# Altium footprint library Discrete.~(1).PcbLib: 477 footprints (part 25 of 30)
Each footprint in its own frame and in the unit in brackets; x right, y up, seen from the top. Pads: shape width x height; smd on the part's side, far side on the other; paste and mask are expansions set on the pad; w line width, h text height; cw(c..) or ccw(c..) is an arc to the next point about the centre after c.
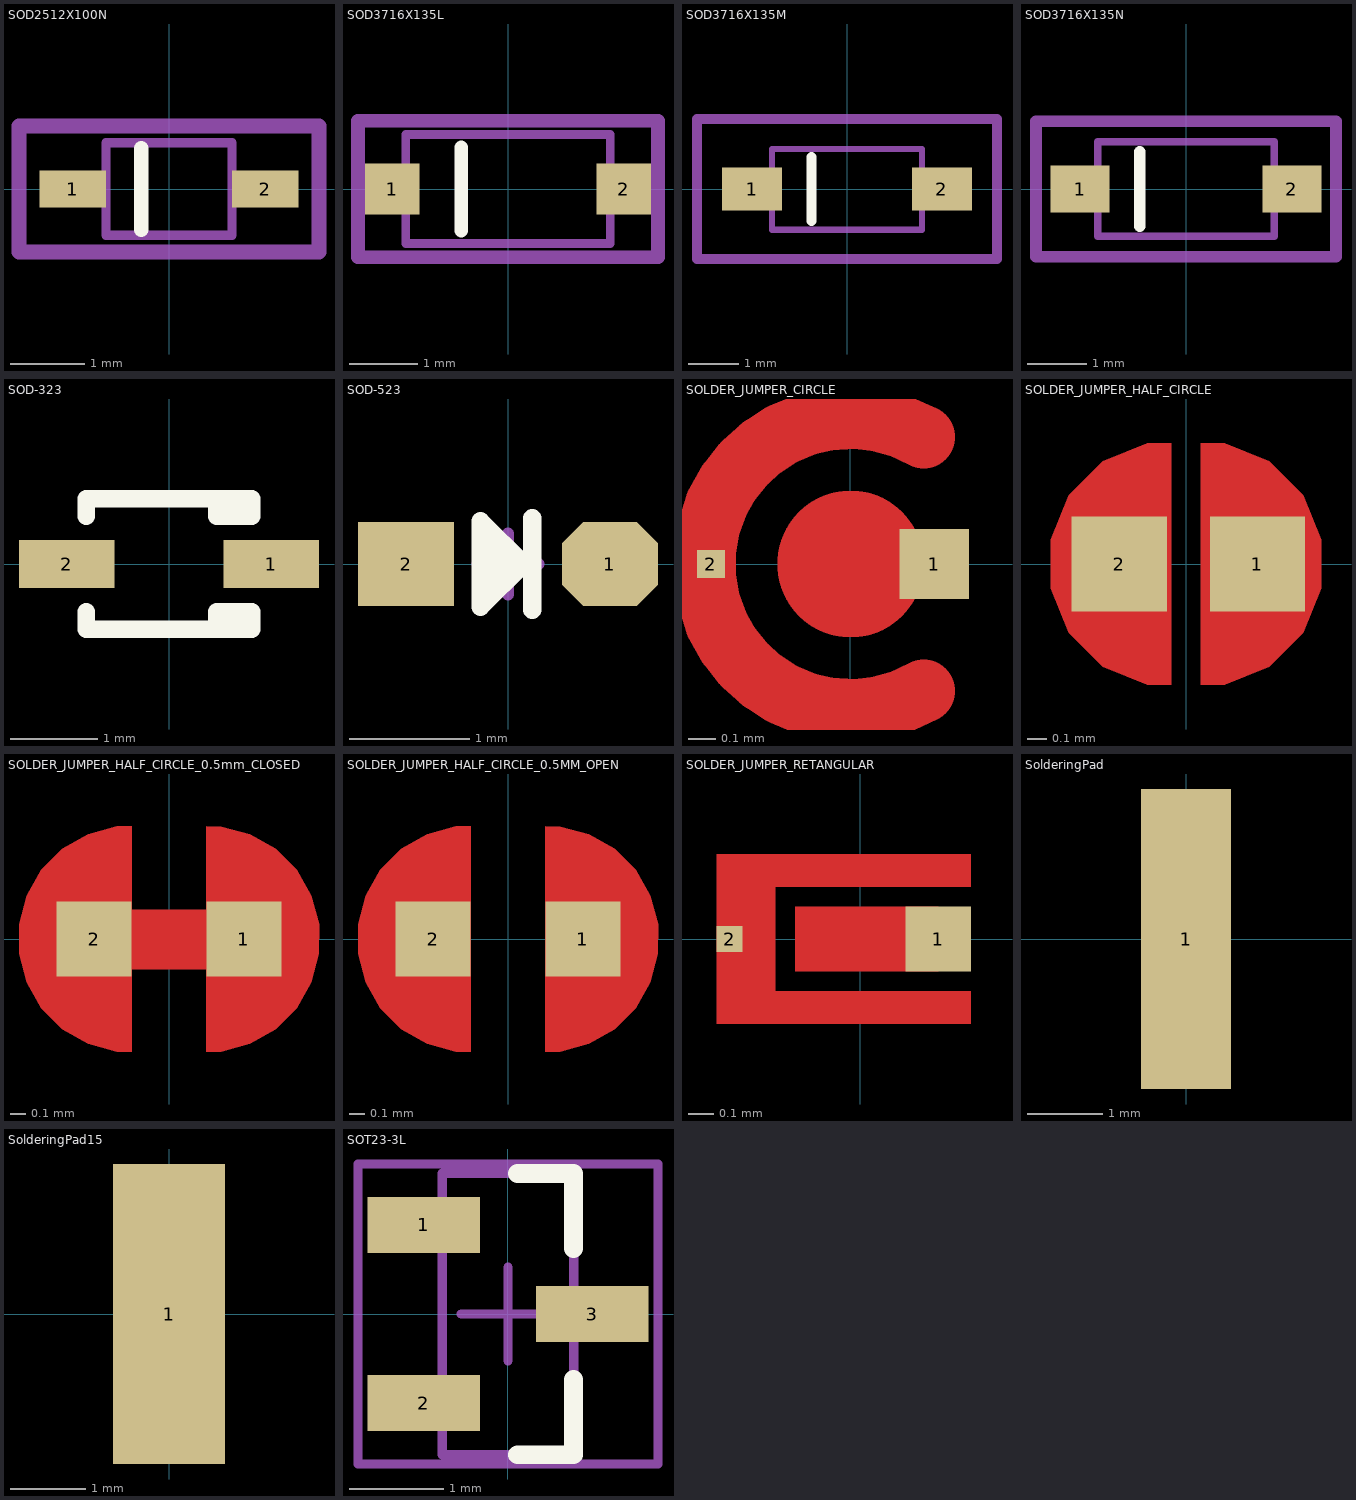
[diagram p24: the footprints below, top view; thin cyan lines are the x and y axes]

## SOD2512X100N [mm] "SOD Diode: SOD-323"
height 1
pads (2):
  rect 0.9x0.5 smd: 1(-1.3,0) 2(1.3,0)
Top Overlay:
  lines w0.2: -0.375,-0.55 -0.375,0.55
Mechanical 13:
  lines w0.127: -0.85,-0.625 -0.85,0.625 0.85,0.625 0.85,-0.625 -0.85,-0.625
Mechanical 15:
  lines w0.2: -2.025,-0.85 -2.025,0.85 2.025,0.85 2.025,-0.85 -2.025,-0.85
3D body "SOD-323.STEP": height 1, standoff 0.04, extent -1.324,-0.65 1.324,0.65

## SOD3716X135L [mm] "SOD Diode: SOD-123"
pads (2):
  rect 0.8x0.75 smd: 1(-1.7,0) 2(1.7,0)
Top Overlay:
  lines w0.2: -0.686,-0.61 -0.686,0.61
Mechanical 13:
  lines w0.127: -1.5,-0.8 1.5,-0.8 1.5,0.8 -1.5,0.8 -1.5,-0.8
Mechanical 15:
  lines w0.2: -2.2,-1 2.2,-1 2.2,1 -2.2,1 -2.2,-1
3D body "SOD-123.STEP": height 1.22, standoff 0, extent -1.85,-0.8 1.85,0.8

## SOD3716X135M [mm] "SOD Diode: SOD-123"
pads (2):
  rect 1.2x0.85 smd: 1(-1.9,0) 2(1.9,0)
Top Overlay:
  lines w0.2: -0.711,-0.635 -0.711,0.635
Mechanical 13:
  lines w0.127: -1.5,-0.813 -1.5,0.8 1.5,0.8 1.5,-0.813 -1.5,-0.813
Mechanical 15:
  lines w0.2: -3,-1.4 -3,1.4 3,1.4 3,-1.4 -3,-1.4
3D body "SOD-123.STEP": height 1.22, standoff 0, extent -1.85,-0.8 1.85,0.8

## SOD3716X135N [mm] "SOD Diode: SOD-123"
pads (2):
  rect 1x0.8 smd: 1(-1.8,0) 2(1.8,0)
Top Overlay:
  lines w0.2: -0.787,-0.635 -0.787,0.635
Mechanical 13:
  lines w0.127: -1.5,-0.8 1.5,-0.8 1.5,0.8 -1.5,0.8 -1.5,-0.8
Mechanical 15:
  lines w0.2: -2.55,-1.15 2.55,-1.15 2.55,1.15 -2.55,1.15 -2.55,-1.15
3D body "SOD-123.STEP": height 1.22, standoff 0, extent -1.85,-0.8 1.85,0.8

## SOD-323 [mm] "SOD-323/SC-76; 2 Leads; Body 1.7 x 1.3 mm, (LxW)"
height 1.1
pads (2):
  rect 1.1x0.55 smd: 1(1.175,0) 2(-1.175,0)
Top Overlay:
  lines w0.2: -0.95,-0.55 -0.95,-0.75 0.95,-0.75 0.95,-0.55 0.55,-0.55 0.55,-0.75 ; -0.95,0.55 -0.95,0.75 0.95,0.75 0.95,0.55 0.55,0.55 0.55,0.75
3D body "SOD-323.STEP": height 1, standoff 0.04, extent -1.337,-0.631 1.311,0.669

## SOD-523 [mm] "1.2x0.8X0.6mm（长宽高，不包括引脚）"
pads (2):
  oct 0.8x0.7 smd: 1(0.85,0)
  rect 0.8x0.7 smd: 2(-0.85,0)
Top Overlay:
  rectangle: -0.178,-0.178 0,0.178
  lines w0.152: -0.127,0 0.127,0 ; 0.203,-0.381 0.203,0.381 ; 0.127,0 -0.229,0.356 -0.229,-0.356 0.127,0
Mechanical 15:
  lines w0.1: -0.254,0 0.254,0 ; 0,-0.254 0,0.254
3D body "SOD-523.STEP": height 0.65, standoff 0.05, extent -0.8,-0.4 0.8,0.4

## SOIL_SENSOR_PATTERN_1 [mm]

## SOLDER_JUMPER_CIRCLE [mil]
pads (2):
  rect 10x10 smd: 1(12,0)
  rect 4x4 smd mask+0: 2(-20,0)
Top Layer:
  circle w19: c0,0 r1
  lines w9: 10.5,-18.19 cw(c0,0) 10.5,18.19
Top Solder:
  circle w40: c0,0 r7.07

## SOLDER_JUMPER_HALF_CIRCLE [mm]
pads (2):
  rect 0.5x0.5 smd: 1(0.375,0) 2(-0.35,0)
Top Layer:
  region: 0.076,-0.635 0.203,-0.635 0.436,-0.538 0.615,-0.36 0.711,-0.126 0.711,0.126 0.615,0.36 0.436,0.538 0.203,0.635 0.076,0.635
  region: -0.076,-0.635 -0.203,-0.635 -0.436,-0.538 -0.615,-0.36 -0.711,-0.126 -0.711,0.126 -0.615,0.36 -0.436,0.538 -0.203,0.635 -0.076,0.635
Top Solder:
  region: -0.076,-0.711 -0.17,-0.711 -0.351,-0.663 -0.513,-0.569 -0.645,-0.437 -0.739,-0.275 -0.787,-0.094 -0.787,0.094 -0.739,0.275 -0.645,0.437 -0.513,0.569 -0.351,0.663 -0.17,0.711 -0.076,0.711 0.076,0.711 0.17,0.711 0.351,0.663 0.513,0.569 0.645,0.437 0.739,0.275 0.787,0.094 0.787,-0.094 0.739,-0.275 0.645,-0.437 0.513,-0.569 0.351,-0.663 0.17,-0.711 0.076,-0.711

## SOLDER_JUMPER_HALF_CIRCLE_0.5mm_CLOSED [mm]
pads (2):
  rect 0.5x0.5 smd: 1(0.5,0) 2(-0.5,0)
Top Layer:
  region: 0.25,-0.75 0.349,-0.75 0.539,-0.699 0.711,-0.6 0.85,-0.461 0.949,-0.289 1,-0.099 1,0.099 0.949,0.289 0.85,0.461 0.711,0.6 0.539,0.699 0.349,0.75 0.25,0.75
  region: -0.25,-0.75 -0.349,-0.75 -0.539,-0.699 -0.711,-0.6 -0.85,-0.461 -0.949,-0.289 -1,-0.099 -1,0.099 -0.949,0.289 -0.85,0.461 -0.711,0.6 -0.539,0.699 -0.349,0.75 -0.25,0.75
  lines w0.4: -0.25,-0.003 0.492,-0.003
Top Solder:
  rectangle: -0.25,-0.25 0.25,0.25

## SOLDER_JUMPER_HALF_CIRCLE_0.5MM_OPEN [mm]
pads (2):
  rect 0.5x0.5 smd: 1(0.5,0) 2(-0.5,0)
Top Layer:
  region: -0.25,-0.75 -0.349,-0.75 -0.539,-0.699 -0.711,-0.6 -0.85,-0.461 -0.949,-0.289 -1,-0.099 -1,0.099 -0.949,0.289 -0.85,0.461 -0.711,0.6 -0.539,0.699 -0.349,0.75 -0.25,0.75
  region: 0.25,-0.75 0.349,-0.75 0.539,-0.699 0.711,-0.6 0.85,-0.461 0.949,-0.289 1,-0.099 1,0.099 0.949,0.289 0.85,0.461 0.711,0.6 0.539,0.699 0.349,0.75 0.25,0.75

## SOLDER_JUMPER_RETANGULAR [mil]
pads (2):
  rect 10x10 smd: 1(12,0)
  rect 4x4 smd mask+0: 2(-20,0)
Top Layer:
  rectangle: -22,-13 17,-8
  rectangle: -22,8 17,13
  rectangle: -22,-10 -13,10
  rectangle: -10,-5 12,5
Top Solder:
  rectangle: -25,-15 21,15

## SolderingPad [mm]
pads (1):
  rect 1.2x4 smd: 1(0,0)

## SolderingPad15 [mm]
pads (1):
  rect 1.5x4 smd: 1(0,0)

## SolderingPads [mm]

## SOT23-3L [mm] "SOT23, 3-Leads, Body 2.9x1.3mm, Pitch 0.95mm, Lead Span 2.5mm, IPC High Density"
height 1.1
pads (3):
  rect 1.2x0.6 smd: 1(-0.9,0.95) 2(-0.9,-0.95) 3(0.9,0)
Top Overlay:
  lines w0.2: 0.1,-1.5 0.7,-1.5 0.7,-0.7 ; 0.1,1.5 0.7,1.5 0.7,0.7
Mechanical 13:
  lines w0.1: -0.7,-1.5 0.7,-1.5 0.7,1.5 -0.7,1.5 -0.7,-1.5
Mechanical 15:
  lines w0.1: -0.5,0 0.5,0 ; 0,-0.5 0,0.5 ; -1.6,-1.6 1.6,-1.6 1.6,1.6 -1.6,1.6 -1.6,-1.6
3D body "SOT23.STEP": height 1.08, standoff 0, extent -1.295,-1.5 1.345,1.5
